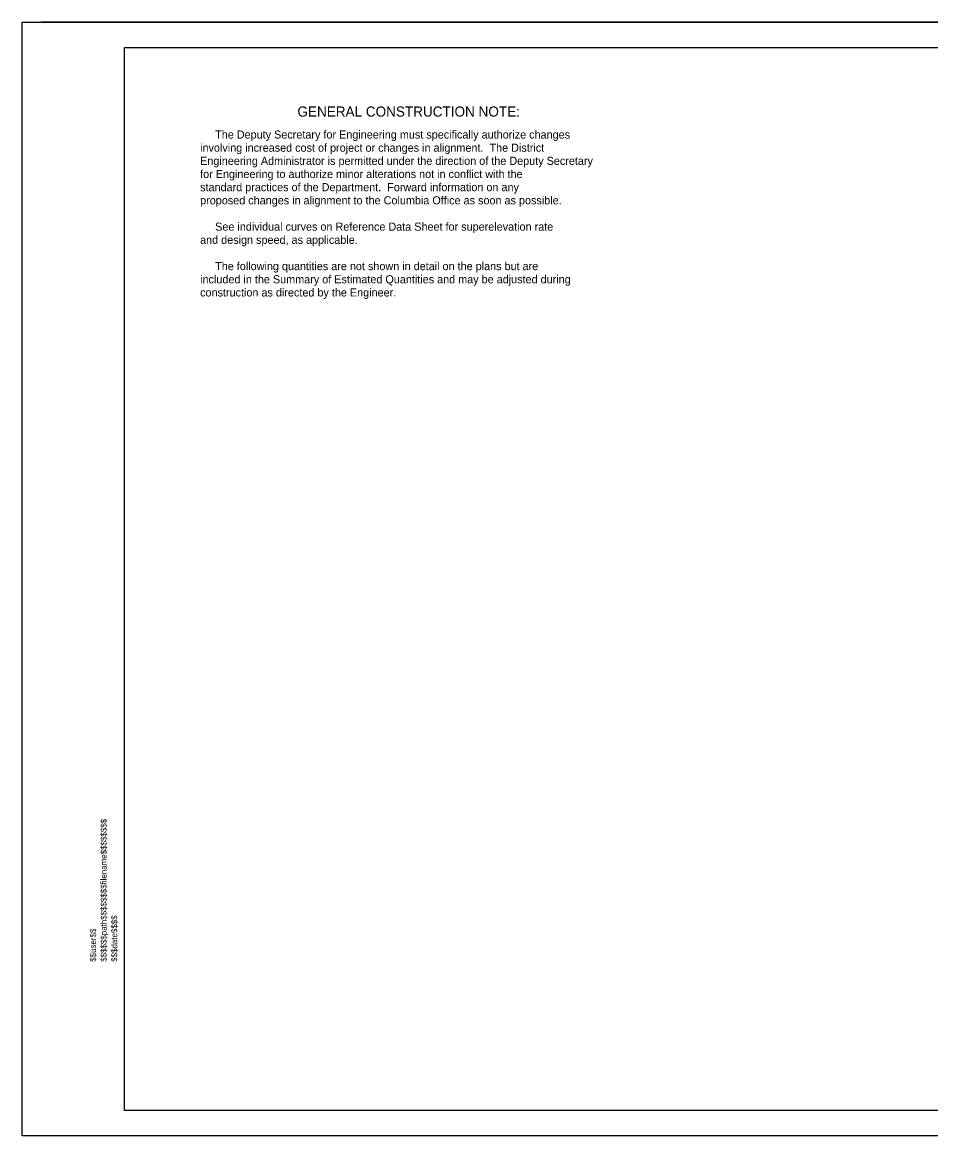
# Model space of a CAD drawing. Extents: x -796 to 2793, y -4650 to 4425.
# Drawn here: x 981 to 1879, y -3500 to -2400 of the extents above; entities that cross this region are included whole.
import ezdxf

# ---------------------------------------------------------------- set-up
doc = ezdxf.new("R2010")
doc.units = 0
for name, color, linetype in [('RD_HC_CL', 7, 'Continuous'), ('RD_HC_Data', 7, 'Continuous'), ('RD_TX_Misc1', 7, 'Continuous'), ('RD_TX_Qty', 7, 'Continuous')]:
    doc.layers.add(name, color=color, linetype=linetype)

msp = doc.modelspace()

# ---------------------------------------------------------------- linework, layer by layer
at = {"layer": 'RD_HC_CL'}
msp.add_lwpolyline([(981.4, -2400), (2777.4, -2400), (2777.4, -3500), (981.4, -3500)], close=True, dxfattribs=at)
at = {"layer": 'RD_HC_Data'}
for p, q in [((2760, -2400), (1000, -2400)), ((1000, -2400), (2760, -2400)), ((2760, -3500), (1000, -3500)), ((2760, -3500), (1000, -3500))]:
    msp.add_line(p, q, dxfattribs=at)
msp.add_lwpolyline([(1082.6, -2425), (2757.6, -2425), (2757.6, -3475), (1082.6, -3475)], close=True, dxfattribs=at)

# ---------------------------------------------------------------- texts
at = {"layer": 'RD_TX_Misc1'}
for s, p in [('$$$$$$path$$$$$$$$filename$$$$$$$$', (1064.8, -3328.2)), ('$$$date$$$$', (1075.3, -3328.2)), ('$$user$$', (1054.3, -3328.2))]:
    msp.add_text(s, height=5.88, rotation=90, dxfattribs=at).set_placement(p)
at = {"layer": 'RD_TX_Qty'}
for s, height, p in [('GENERAL CONSTRUCTION NOTE:', 10, (1253.4, -2493.2)), ('     The Deputy Secretary for Engineering must specifically authorize changes', 8, (1157.2, -2514.9)), ('involving increased cost of project or changes in alignment.  The District', 8, (1157.2, -2527.9)), ('Engineering Administrator is permitted under the direction of the Deputy Secretary', 8, (1157.2, -2540.9)), ('for Engineering to authorize minor alterations not in conflict with the', 8, (1157.2, -2553.9)), ('standard practices of the Department.  Forward information on any', 8, (1157.2, -2566.9)), ('proposed changes in alignment to the Columbia Office as soon as possible.', 8, (1157.2, -2579.9)), ('     See individual curves on Reference Data Sheet for superelevation rate', 8, (1157.2, -2605.9)), ('and design speed, as applicable.', 8, (1157.2, -2618.9)), ('     The following quantities are not shown in detail on the plans but are', 8, (1157.2, -2644.9)), ('included in the Summary of Estimated Quantities and may be adjusted during', 8, (1157.2, -2657.9)), ('construction as directed by the Engineer.', 8, (1157.2, -2670.9))]:
    msp.add_text(s, height=height, dxfattribs=at).set_placement(p)

doc.saveas('drawing.dxf')
